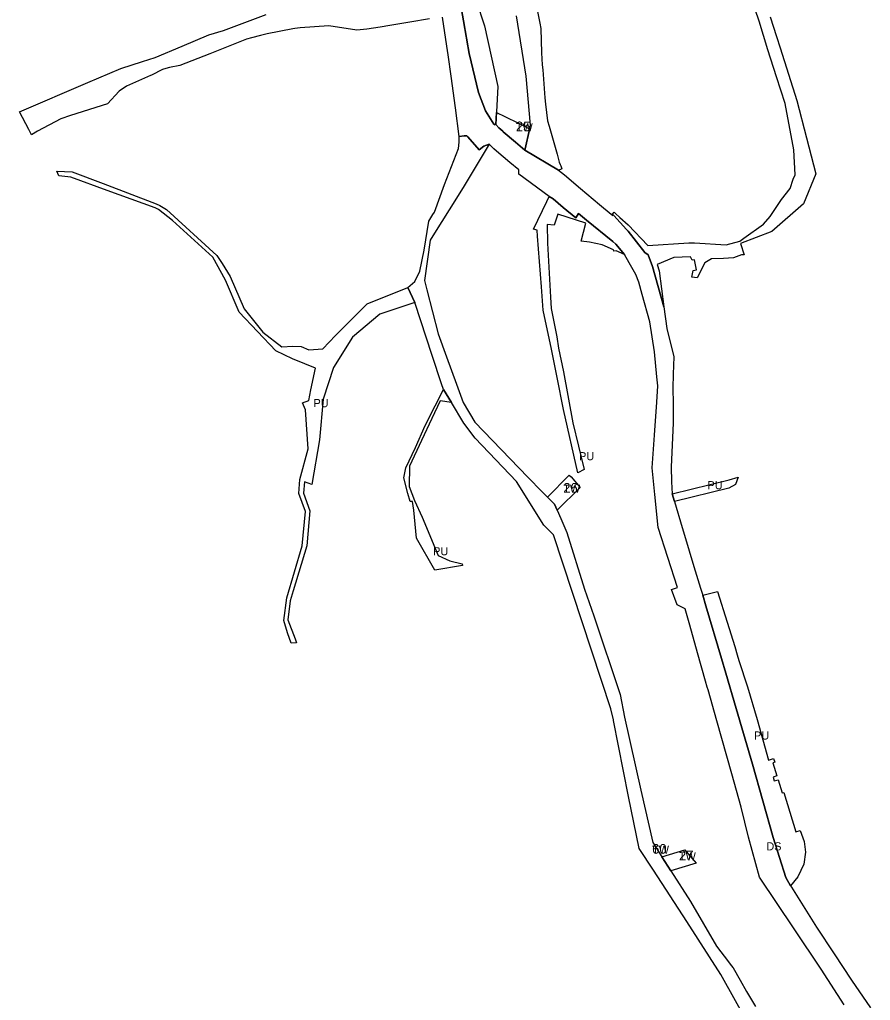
# Model space of a CAD drawing. Extents: x -519992 to -518210, y -1182334 to -1179965.
# Drawn here: x -519734 to -519211, y -1181730 to -1181126 of the extents above; entities that cross this region are included whole.
import ezdxf

# ---------------------------------------------------------------- set-up
doc = ezdxf.new("R2010")
doc.units = 0
for name, color, linetype in [('90320013', 7, 'Continuous'), ('90390023', 7, 'Continuous'), ('90450013', 7, 'Continuous'), ('ID_navrh', 7, 'Continuous')]:
    doc.layers.add(name, color=color, linetype=linetype)

msp = doc.modelspace()

# ---------------------------------------------------------------- linework, layer by layer
at = {"layer": '90320013'}
for points in [[(-519463.67, -1181111.66), (-519461.06, -1181126.84), (-519458.218, -1181143.324), (-519457.6, -1181146.91), (-519451.79, -1181170.93), (-519447.51, -1181182.1), (-519442.35, -1181190.3), (-519441.96, -1181190.81), (-519441.4, -1181190.32), (-519441.19, -1181190.55), (-519439.29, -1181192.58), (-519436.97, -1181194.76), (-519436.64, -1181195.05), (-519429.02, -1181201.47), (-519423.236, -1181206.354), (-519402.57, -1181218.61), (-519398.99, -1181221.63), (-519389.03, -1181229.99), (-519377.33, -1181239.82), (-519370.22, -1181245.81), (-519369.14, -1181246.71), (-519369.41, -1181245.84), (-519368.6, -1181246.7), (-519360.66, -1181255.15), (-519359.8, -1181256.24), (-519349.4, -1181269.34), (-519347.5, -1181270.88), (-519344.68, -1181278.08), (-519337.67, -1181302.8), (-519335.92, -1181316.27), (-519331.61, -1181333.64), (-519331.914, -1181344.262), (-519332.16, -1181352.86), (-519332.1, -1181362.29), (-519331.94, -1181374.47), (-519333.17, -1181401.37), (-519332.97, -1181410.48), (-519332.65, -1181417.95), (-519331.26, -1181422.58), (-519326.45, -1181438.74), (-519325.1, -1181443.3), (-519319.3, -1181462.74), (-519315.25, -1181475.99), (-519313.79, -1181480.37), (-519311.85, -1181486.94), (-519302.26, -1181519.38), (-519299.654, -1181528.266), (-519293.22, -1181550.2), (-519283.11, -1181584.4), (-519270.47, -1181629.49), (-519262.7, -1181654.09), (-519259.83, -1181659.23), (-519259.16, -1181660.01), (-519243.72, -1181684.69), (-519232.85, -1181701.16), (-519222.31, -1181717.35), (-519210.59, -1181734.41)], [(-519226.78, -1181732.6), (-519240.87, -1181710.49), (-519257.5, -1181685.66), (-519278.9, -1181653.87), (-519285.66, -1181629.38), (-519290.23, -1181610.77), (-519295.83, -1181590.22), (-519305.13, -1181557.6), (-519310.53, -1181538.55), (-519311.02, -1181536.87), (-519312.06, -1181533.32), (-519316.93, -1181515.86), (-519321.66, -1181498.89), (-519324.61, -1181488.84), (-519329.64, -1181486.36), (-519332.99, -1181476.91), (-519329.41, -1181475.65), (-519341.26, -1181438.76), (-519343.34, -1181418.43), (-519345.02, -1181401.88), (-519343.53, -1181381.92), (-519342, -1181361.53), (-519341.52, -1181351.55), (-519342.073, -1181345.845), (-519343.55, -1181330.6), (-519346.33, -1181312), (-519351.06, -1181295.22), (-519353.22, -1181287.56), (-519355.01, -1181282.89), (-519359, -1181275.67), (-519361.88, -1181270.58), (-519367.28, -1181264.25), (-519369.19, -1181262.7), (-519385.44, -1181249.52), (-519390.25, -1181245.38), (-519391.89, -1181248.03), (-519399.69, -1181241.74), (-519405.93, -1181236.31), (-519408.44, -1181234.99), (-519427.12, -1181221.16), (-519427.07, -1181218.6), (-519432.6, -1181213.97), (-519440.69, -1181206.91), (-519442.35, -1181205.48), (-519445.38, -1181202.73), (-519448.54, -1181203.93), (-519451.39, -1181206.26), (-519458.36, -1181198.19), (-519458.98, -1181197.47), (-519460.75, -1181197.6), (-519463.761, -1181197.967), (-519466.06, -1181180.23), (-519468.7, -1181160.79), (-519470.625, -1181147.693), (-519471.4, -1181142.42), (-519474.11, -1181124.5)]]:
    msp.add_lwpolyline(points, dxfattribs=at)
at = {"layer": '90390023'}
for points in [[(-519427.239, -1181189.828), (-519420.397, -1181193.163), (-519420.494, -1181193.616), (-519423.04, -1181205.49), (-519423.236, -1181206.354), (-519429.02, -1181201.47), (-519436.64, -1181195.05), (-519436.97, -1181194.76), (-519439.29, -1181192.58), (-519441.19, -1181190.55), (-519440.793, -1181183.221), (-519435.742, -1181185.683)], [(-519389.322, -1181414.013), (-519403.401, -1181428.069), (-519405.11, -1181424.27), (-519409.389, -1181419.917), (-519395.935, -1181406.485), (-519394.88, -1181407.4)], [(-519317.776, -1181645.284), (-519333.365, -1181650.082), (-519338.936, -1181641.334), (-519324.89, -1181637.01), (-519324.89, -1181637.01), (-519321.97, -1181640.55)]]:
    msp.add_lwpolyline(points, close=True, dxfattribs=at)
msp.add_lwpolyline([(-519277.686, -1181758.823), (-519302.615, -1181713.865), (-519323.558, -1181681.236), (-519344.18, -1181649.622), (-519352.882, -1181636.283), (-519359.552, -1181604.298), (-519368.666, -1181557.487), (-519368.731, -1181557.154), (-519370.38, -1181550.34), (-519405.66, -1181443.112), (-519411.67, -1181437.16), (-519428.48, -1181410.32), (-519453.99, -1181383.61), (-519460.96, -1181374.51), (-519468.38, -1181361.8), (-519473.49, -1181353.7), (-519474.62, -1181350.3), (-519480.35, -1181332.79), (-519490.95, -1181300.08), (-519495.45, -1181291.01), (-519491.07, -1181287.18), (-519488.02, -1181280.85), (-519485.36, -1181267.89), (-519482.42, -1181250.06), (-519479.89, -1181246.03), (-519478.94, -1181244.53), (-519472.72, -1181227.62), (-519464.27, -1181205.34), (-519463.77, -1181201.39), (-519463.67, -1181198.67), (-519463.761, -1181197.967), (-519460.75, -1181197.6), (-519458.98, -1181197.47), (-519458.36, -1181198.19), (-519451.39, -1181206.26), (-519448.54, -1181203.93), (-519445.38, -1181202.73), (-519450.28, -1181210.83), (-519460.68, -1181228.41), (-519464.29, -1181234.25), (-519479.97, -1181259.11), (-519481.6, -1181261.79), (-519485.03, -1181286.53), (-519483.7, -1181292.46), (-519476.71, -1181319.53), (-519471.53, -1181333.7), (-519465.42, -1181350.42), (-519461.32, -1181361.65), (-519454.05, -1181373.8), (-519421.56, -1181407.62), (-519412.61, -1181416.64), (-519409.389, -1181419.917), (-519405.11, -1181424.27), (-519403.401, -1181428.069), (-519401.11, -1181433.16), (-519397.54, -1181441.8), (-519386.52, -1181476.56), (-519380.95, -1181493.03), (-519364.56, -1181541.56), (-519362.01, -1181555.36), (-519351.95, -1181600.47), (-519344.46, -1181632.66), (-519338.936, -1181641.334), (-519333.365, -1181650.082), (-519321.38, -1181668.9), (-519305.33, -1181696.42), (-519298.01, -1181706.05), (-519296.21, -1181708.36), (-519295.09, -1181709.75), (-519290.763, -1181717.333), (-519286.8, -1181724.28), (-519281.3, -1181733.63)], dxfattribs=at)
at = {"layer": '90450013'}
for points in [[(-519458.37, -1181098.48), (-519448.2, -1181129.83), (-519439.93, -1181167.27), (-519441.19, -1181190.55), (-519441.4, -1181190.32), (-519441.96, -1181190.81), (-519442.35, -1181190.3), (-519447.51, -1181182.1), (-519451.79, -1181170.93), (-519457.6, -1181146.91), (-519461.06, -1181126.84), (-519463.67, -1181111.66)], [(-519417.22, -1181112.52), (-519414.06, -1181128.16), (-519413.48, -1181131.53), (-519413.13, -1181146.55), (-519412.58, -1181153.94), (-519412.3, -1181156.89), (-519411.08, -1181174.15), (-519410.64, -1181178.03), (-519409.3, -1181188.38), (-519408.409, -1181191.549), (-519403.52, -1181208.94), (-519402.1, -1181213.73), (-519401.58, -1181215.19), (-519401.26, -1181216.12), (-519400.61, -1181217.94), (-519401.33, -1181218.2), (-519402.57, -1181218.61), (-519423.236, -1181206.354), (-519423.04, -1181205.49), (-519420.494, -1181193.616), (-519419.92, -1181190.94), (-519422.52, -1181160.74), (-519428.49, -1181123.78)], [(-519482.04, -1181125.48), (-519494.21, -1181127.6), (-519506.51, -1181129.69), (-519512.47, -1181130.64), (-519520.68, -1181131.92), (-519526.81, -1181132.58), (-519543.98, -1181129.89), (-519561.71, -1181131.12), (-519564.86, -1181131.53), (-519566.07, -1181131.69), (-519582.04, -1181134.87), (-519586.06, -1181135.85), (-519591.67, -1181137.22), (-519594.74, -1181138.08), (-519617.26, -1181147.1), (-519635.82, -1181154.19), (-519642.15, -1181155.58), (-519644.31, -1181156.13), (-519646.41, -1181156.68), (-519653.21, -1181160.19), (-519653.86, -1181160.48), (-519668.56, -1181167.09), (-519673.02, -1181170.06), (-519680.21, -1181177.92), (-519702.97, -1181185.1), (-519708.94, -1181187.08), (-519723.4, -1181194.69), (-519726.953, -1181197.019), (-519728.68, -1181193.73), (-519734.37, -1181182.89), (-519692.32, -1181164.66), (-519672.04, -1181156.22), (-519658.72, -1181151.87), (-519650.95, -1181149.39), (-519634.27, -1181142.3), (-519617.88, -1181135.45), (-519608.92, -1181132.65), (-519582.6, -1181122.9)], [(-519272.32, -1181124.33), (-519268.33, -1181136.35), (-519266.11, -1181143.37), (-519255.92, -1181175.76), (-519249.99, -1181198.85), (-519244.13, -1181221), (-519251.84, -1181239.51), (-519271.34, -1181256.39), (-519290.48, -1181263.76), (-519288.24, -1181270.77), (-519289.86, -1181270.92), (-519294.94, -1181272.61), (-519301, -1181273.11), (-519308.46, -1181273.24), (-519312.48, -1181275.65), (-519317.31, -1181285.07), (-519320.45, -1181284.58), (-519319.61, -1181280.55), (-519317.66, -1181279.98), (-519318.92, -1181273.8), (-519320.28, -1181274.16), (-519321.33, -1181271.99), (-519331.69, -1181272.48), (-519341.78, -1181276.85), (-519340.55, -1181280.62), (-519337.67, -1181302.8), (-519344.68, -1181278.08), (-519347.5, -1181270.88), (-519349.4, -1181269.34), (-519359.8, -1181256.24), (-519360.66, -1181255.15), (-519368.6, -1181246.7), (-519369.41, -1181245.84), (-519368.27, -1181244.63), (-519367.47, -1181245.36), (-519364.85, -1181247.77), (-519359.8, -1181252.34), (-519347.58, -1181265.14), (-519322.38, -1181263.46), (-519318.92, -1181263.47), (-519299.44, -1181264.69), (-519291.02, -1181262.32), (-519288.53, -1181260.56), (-519276.43, -1181252.01), (-519272.39, -1181247.3), (-519265.3, -1181236.77), (-519260.04, -1181229.91), (-519258.16, -1181224.34), (-519256.93, -1181221.56), (-519257.71, -1181206.09), (-519262.98, -1181177.76), (-519268.34, -1181161.26), (-519273.72, -1181144.7), (-519279.05, -1181127), (-519281.47, -1181119.77)]]:
    msp.add_lwpolyline(points, dxfattribs=at)
for points in [[(-519495.45, -1181291.01), (-519490.95, -1181300.08), (-519512.56, -1181307.36), (-519529.45, -1181321.54), (-519541.15, -1181340.2), (-519547.39, -1181359.65), (-519549.83, -1181384.8), (-519554.45, -1181412.24), (-519558.96, -1181410.51), (-519559.59, -1181417.6), (-519555.67, -1181428.4), (-519557.53, -1181449.89), (-519565.97, -1181477.58), (-519567.71, -1181483.82), (-519569.16, -1181495.61), (-519564.79, -1181507.27), (-519563.86, -1181509.62), (-519567.26, -1181509.91), (-519569.38, -1181503.52), (-519571.73, -1181495.99), (-519569.85, -1181481.93), (-519560.34, -1181449.96), (-519558.29, -1181428.74), (-519562.53, -1181417.65), (-519561.9, -1181409.19), (-519556.82, -1181390.16), (-519558.28, -1181366.15), (-519560.15, -1181361.95), (-519556.37, -1181360.48), (-519555.04, -1181353.99), (-519552.26, -1181340.67), (-519558.73, -1181337.98), (-519566.39, -1181334.81), (-519576.62, -1181329.91), (-519599.24, -1181306.16), (-519607.62, -1181286.42), (-519615.51, -1181272.35), (-519640.15, -1181249.77), (-519648.79, -1181242.92), (-519650.9, -1181241.93), (-519680.5, -1181231.13), (-519702.88, -1181223.02), (-519710.22, -1181222.14), (-519711.37, -1181219.26), (-519702.08, -1181219.82), (-519683.02, -1181226.97), (-519650.25, -1181239.39), (-519648.08, -1181240.45), (-519643.87, -1181242.87), (-519613, -1181271.17), (-519609.76, -1181276.13), (-519604.82, -1181284.25), (-519596.14, -1181304.15), (-519584.59, -1181318.45), (-519572.95, -1181327.41), (-519566.09, -1181327.12), (-519560.98, -1181327.2), (-519556.37, -1181329.29), (-519547.62, -1181328.79), (-519539.81, -1181320.48), (-519520.31, -1181300.89)], [(-519367.28, -1181264.25), (-519361.88, -1181270.58), (-519367.12, -1181268.35), (-519368.61, -1181268.51), (-519368.69, -1181267.68), (-519375.73, -1181264.7), (-519383.43, -1181263.05), (-519388.7, -1181262.33), (-519385.82, -1181251.37), (-519403.09, -1181245.73), (-519405.35, -1181252.48), (-519409.67, -1181252.22), (-519409.3, -1181263.68), (-519407.54, -1181296.85), (-519407.18, -1181303.84), (-519403.64, -1181321.37), (-519402.53, -1181328.3), (-519399.57, -1181342.94), (-519393.68, -1181374.33), (-519386.81, -1181402.99), (-519390.78, -1181404.99), (-519399.59, -1181366.06), (-519403.5, -1181346.27), (-519406.83, -1181328.84), (-519412.01, -1181304.84), (-519413.09, -1181290.54), (-519414.4, -1181274.83), (-519415.63, -1181259.28), (-519415.78, -1181255.68), (-519417.95, -1181255.02), (-519409.72, -1181237.91), (-519408.44, -1181234.99), (-519405.93, -1181236.31), (-519399.69, -1181241.74), (-519391.89, -1181248.03), (-519390.25, -1181245.38), (-519385.44, -1181249.52), (-519369.19, -1181262.7)], [(-519473.49, -1181353.7), (-519468.38, -1181361.8), (-519475.44, -1181360.75), (-519480.54, -1181371.6), (-519486.92, -1181385.2), (-519494.32, -1181400.97), (-519494.57, -1181413.52), (-519491.16, -1181422.01), (-519486.55, -1181432.38), (-519476.59, -1181455.99), (-519469.53, -1181459.21), (-519461.99, -1181461.06), (-519461.71, -1181462.1), (-519478.73, -1181464.87), (-519490.11, -1181445.28), (-519491.71, -1181427.92), (-519492.41, -1181422.69), (-519493.91, -1181422.63), (-519495.36, -1181417.71), (-519497.81, -1181408), (-519496.69, -1181401.85), (-519490.69, -1181389.39), (-519484.77, -1181375.79), (-519478.53, -1181363.83)], [(-519291.91, -1181407.72), (-519293.55, -1181412.29), (-519297.82, -1181414.5), (-519331.26, -1181422.58), (-519332.65, -1181417.95), (-519297.56, -1181409.41)], [(-519256.49, -1181625.97), (-519253.84, -1181625.29), (-519251.26, -1181632.02), (-519250.58, -1181638.56), (-519251.54, -1181645.91), (-519255.19, -1181653.78), (-519259.83, -1181659.23), (-519262.7, -1181654.09), (-519270.47, -1181629.49), (-519283.11, -1181584.4), (-519293.22, -1181550.2), (-519299.654, -1181528.266), (-519302.26, -1181519.38), (-519311.85, -1181486.94), (-519313.79, -1181480.37), (-519304.65, -1181478.09), (-519298.75, -1181496.87), (-519294.09, -1181512), (-519292.63, -1181517.01), (-519291.503, -1181520.559), (-519286.34, -1181536.82), (-519280.35, -1181556.91), (-519273.28, -1181581.85), (-519270.22, -1181580.93), (-519269.52, -1181583.22), (-519270.7, -1181583.6), (-519268.18, -1181591.61), (-519270.53, -1181592.34), (-519269.78, -1181594.73), (-519267.44, -1181593.99), (-519264.91, -1181602.05), (-519263.89, -1181601.73)]]:
    msp.add_lwpolyline(points, close=True, dxfattribs=at)

# ---------------------------------------------------------------- texts
at = {"layer": '90320013'}
msp.add_text('DS', height=5, rotation=0, dxfattribs=at).set_placement((-519274.624, -1181637.4469))
at = {"layer": '90390023'}
for rotation, p in [(0, (-519428.8419, -1181194.7875)), (0, (-519399.668, -1181417.277)), (360, (-519344.945, -1181639.5125)), (0, (-519328.4215, -1181643.546))]:
    msp.add_text('TW', height=5, rotation=rotation, dxfattribs=at).set_placement(p)
at = {"layer": '90450013'}
for rotation, p in [(360, (-519553.4228, -1181364.585)), (360, (-519389.915, -1181397.2955)), (360, (-519310.8276, -1181415.15)), (0, (-519479.76, -1181455.7862)), (0, (-519282.185, -1181569.2276))]:
    msp.add_text('PU', height=5, rotation=rotation, dxfattribs=at).set_placement(p)
at = {"layer": 'ID_navrh'}
for s, rotation, p in [('25', 0, (-519428.8419, -1181194.7875)), ('26', 0, (-519399.668, -1181417.277)), ('60', 360, (-519344.945, -1181639.5125)), ('27', 0, (-519328.4215, -1181643.546))]:
    msp.add_text(s, height=6, rotation=rotation, dxfattribs=at).set_placement(p)

doc.saveas('drawing.dxf')
